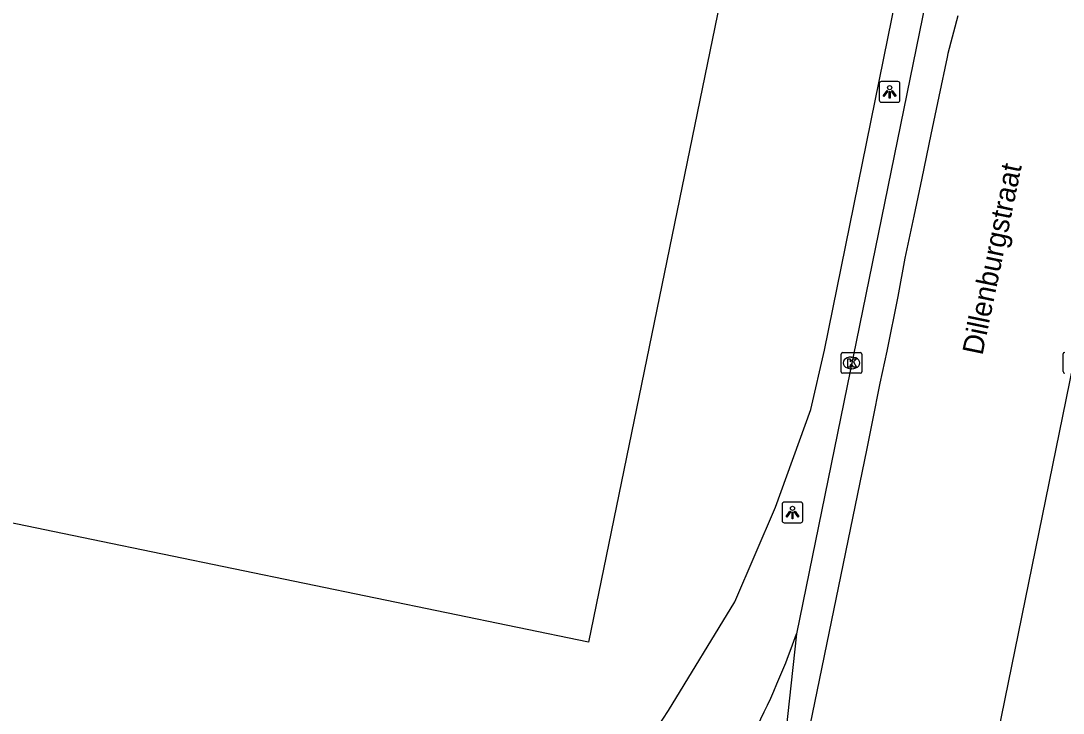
# Model space of a CAD drawing. Extents: x 157692 to 159670, y 381454 to 383289.
# Drawn here: x 158478.6 to 158528.9, y 382152.7 to 382186.1 of the extents above; entities that cross this region are included whole.
import ezdxf

# ---------------------------------------------------------------- set-up
doc = ezdxf.new("R2010")
doc.units = 0
for name, color, linetype in [('IMGEO_Fietspad_gesloten', 7, 'Continuous'), ('IMGEO_Kolk', 7, 'Continuous'), ('IMGEO_Lichtpunt', 7, 'Continuous'), ('IMGEO_Openbare_ruimte_label', 7, 'Continuous'), ('IMGEO_Pand', 7, 'Continuous'), ('IMGEO_Rijbaan_lokaal_gesloten', 7, 'Continuous'), ('IMGEO_Voetpad_open', 7, 'Continuous')]:
    doc.layers.add(name, color=color, linetype=linetype)

msp = doc.modelspace()

# ---------------------------------------------------------------- linework, layer by layer
at = {"layer": 'IMGEO_Fietspad_gesloten'}
msp.add_arc((158481.088, 382168.699), 37.03, 331.5647, 340.7401, dxfattribs=at)
at = {"layer": 'IMGEO_Kolk'}
for p, q in [((158518.203, 382169.132), (158518.203, 382169.984)), ((158518.278, 382170.058), (158519.13, 382170.058)), ((158519.204, 382169.984), (158519.204, 382169.132)), ((158528.926, 382169.138), (158528.926, 382169.99)), ((158518.691, 382169.838), (158518.716, 382169.838)), ((158519.13, 382169.058), (158518.278, 382169.058)), ((158518.714, 382169.278), (158518.689, 382169.278))]:
    msp.add_line(p, q, dxfattribs=at)
for points in [[(158518.203, 382169.132), (158518.203, 382169.984)], [(158518.278, 382170.058), (158519.13, 382170.058)], [(158519.204, 382169.984), (158519.204, 382169.132)], [(158528.926, 382169.138), (158528.926, 382169.99)], [(158518.524, 382169.758), (158518.647, 382169.758), (158518.647, 382169.607), (158518.777, 382169.758), (158518.941, 382169.758), (158518.795, 382169.607), (158518.948, 382169.358), (158518.796, 382169.358), (158518.711, 382169.522), (158518.647, 382169.455), (158518.647, 382169.358), (158518.524, 382169.358), (158518.524, 382169.758)], [(158519.13, 382169.058), (158518.278, 382169.058)]]:
    msp.add_lwpolyline(points, dxfattribs=at)
for centre, start, end in [((158518.28, 382169.982), 91.552, 178.448), ((158518.28, 382169.982), 91.552, 178.448), ((158519.128, 382169.982), 1.552, 88.448), ((158519.128, 382169.982), 1.552, 88.448), ((158529.003, 382169.988), 91.552, 178.448), ((158529.003, 382169.988), 91.552, 178.448), ((158518.28, 382169.134), 181.552, 268.448), ((158518.28, 382169.134), 181.552, 268.448), ((158519.128, 382169.134), 271.552, 358.448), ((158519.128, 382169.134), 271.552, 358.448), ((158529.003, 382169.14), 181.552, 268.448), ((158529.003, 382169.14), 181.552, 268.448)]:
    msp.add_arc(centre, 0.0765, start, end, dxfattribs=at)
for centre, major_axis, ratio, start_param, end_param in [((158518.69, 382169.558), (-0.387, 0.002), 0.722429, 4.712389, 7.853982), ((158518.715, 382169.558), (-0.39, 0.002), 0.717154, 1.570796, 4.712389)]:
    msp.add_ellipse(centre, major_axis=major_axis, ratio=ratio, start_param=start_param, end_param=end_param, dxfattribs=at)
at = {"layer": 'IMGEO_Lichtpunt'}
for p, q in [((158520.046, 382183.041), (158520.046, 382182.234)), ((158520.046, 382183.041), (158520.046, 382182.234)), ((158520.948, 382183.136), (158520.14, 382183.136)), ((158520.948, 382183.136), (158520.14, 382183.136)), ((158521.042, 382182.234), (158521.042, 382183.041)), ((158521.042, 382182.234), (158521.042, 382183.041)), ((158520.14, 382182.14), (158520.948, 382182.14)), ((158520.14, 382182.14), (158520.948, 382182.14)), ((158516.257, 382162.842), (158515.449, 382162.842)), ((158516.257, 382162.842), (158515.449, 382162.842)), ((158515.355, 382162.747), (158515.355, 382161.94)), ((158515.355, 382162.747), (158515.355, 382161.94)), ((158516.351, 382161.94), (158516.351, 382162.747)), ((158516.351, 382161.94), (158516.351, 382162.747)), ((158515.449, 382161.846), (158516.257, 382161.846)), ((158515.449, 382161.846), (158516.257, 382161.846))]:
    msp.add_line(p, q, dxfattribs=at)
for points in [[(158520.42, 382182.705), (158520.459, 382182.677), (158520.271, 382182.415), (158520.233, 382182.442), (158520.42, 382182.705)], [(158520.522, 382182.657), (158520.569, 382182.657), (158520.569, 382182.335), (158520.522, 382182.335), (158520.522, 382182.657)], [(158520.632, 382182.677), (158520.67, 382182.704), (158520.857, 382182.442), (158520.818, 382182.414), (158520.632, 382182.677)], [(158515.729, 382162.411), (158515.768, 382162.383), (158515.58, 382162.121), (158515.542, 382162.148), (158515.729, 382162.411)], [(158515.831, 382162.363), (158515.878, 382162.363), (158515.878, 382162.041), (158515.831, 382162.041), (158515.831, 382162.363)], [(158515.941, 382162.383), (158515.979, 382162.41), (158516.166, 382162.148), (158516.127, 382162.12), (158515.941, 382162.383)]]:
    msp.add_lwpolyline(points, dxfattribs=at)
for centre in [(158520.545, 382182.839), (158515.854, 382162.545)]:
    msp.add_circle(centre, 0.0994, dxfattribs=at)
for centre, start, end in [((158520.14, 382183.041), 90, 180), ((158520.14, 382183.041), 90, 180), ((158520.948, 382183.041), 0, 90), ((158520.948, 382183.041), 0, 90), ((158520.14, 382182.234), 180, 270), ((158520.14, 382182.234), 180, 270), ((158520.948, 382182.234), 270, 0), ((158520.948, 382182.234), 270, 360), ((158515.449, 382162.747), 90, 180), ((158515.449, 382162.747), 90, 180), ((158516.257, 382162.747), 0, 90), ((158516.257, 382162.747), 0, 90), ((158515.449, 382161.94), 180, 270), ((158515.449, 382161.94), 180, 270), ((158516.257, 382161.94), 270, 0), ((158516.257, 382161.94), 270, 360)]:
    msp.add_arc(centre, 0.0946, start, end, dxfattribs=at)
at = {"layer": 'IMGEO_Pand'}
msp.add_lwpolyline([(158518.944, 382219.046), (158505.997, 382156.09), (158482, 382161.038), (158467.988, 382163.933), (158454.893, 382166.763), (158451.663, 382167.461), (158426.084, 382172.727), (158425.284, 382168.853), (158416.078, 382170.753), (158415.87, 382169.745), (158411.493, 382170.649), (158411.724, 382171.766), (158413.743, 382171.35), (158414.515, 382175.094), (158403.487, 382177.37), (158406.581, 382192.364)], dxfattribs=at)
at = {"layer": 'IMGEO_Rijbaan_lokaal_gesloten'}
for points in [[(158522.982, 382137.975), (158549.349, 382267.06), (158553.124, 382285.066), (158561.45, 382326.139), (158561.609, 382326.746), (158561.897, 382327.314), (158562.266, 382327.772), (158562.742, 382328.162), (158563.281, 382328.442), (158563.854, 382328.604), (158564.425, 382328.647), (158564.939, 382328.591), (158565.051, 382328.557)], [(158525.939, 382194.629), (158522.444, 382187.753), (158516.046, 382156.484)], [(158523.847, 382186.302), (158523.361, 382184.485), (158523.324, 382184.31), (158522.925, 382182.414), (158522.54, 382180.58), (158522.095, 382178.467), (158521.711, 382176.637), (158521.285, 382174.615), (158520.949, 382172.76), (158520.406, 382170.124), (158520.067, 382168.58), (158519.695, 382166.711), (158519.44, 382165.43), (158516.351, 382150.416), (158516.345, 382150.4)], [(158516.046, 382156.484), (158515.441, 382150.872)]]:
    msp.add_lwpolyline(points, dxfattribs=at)
at = {"layer": 'IMGEO_Voetpad_open'}
msp.add_lwpolyline([(158509.861, 382152.794), (158513.065, 382158.027), (158515.032, 382162.604), (158516.746, 382167.312), (158517.398, 382170.178), (158524.332, 382204.307), (158524.967, 382207.431), (158524.987, 382207.53)], dxfattribs=at)
msp.add_arc((158459.249, 382185.395), 60.203, 311.86075, 327.21256, dxfattribs=at)

# ---------------------------------------------------------------- texts
at = {"layer": 'IMGEO_Openbare_ruimte_label'}
msp.add_text('Dillenburgstraat', height=1, rotation=78.2855, dxfattribs=at).set_placement((158525.026, 382169.893))

doc.saveas('drawing.dxf')
